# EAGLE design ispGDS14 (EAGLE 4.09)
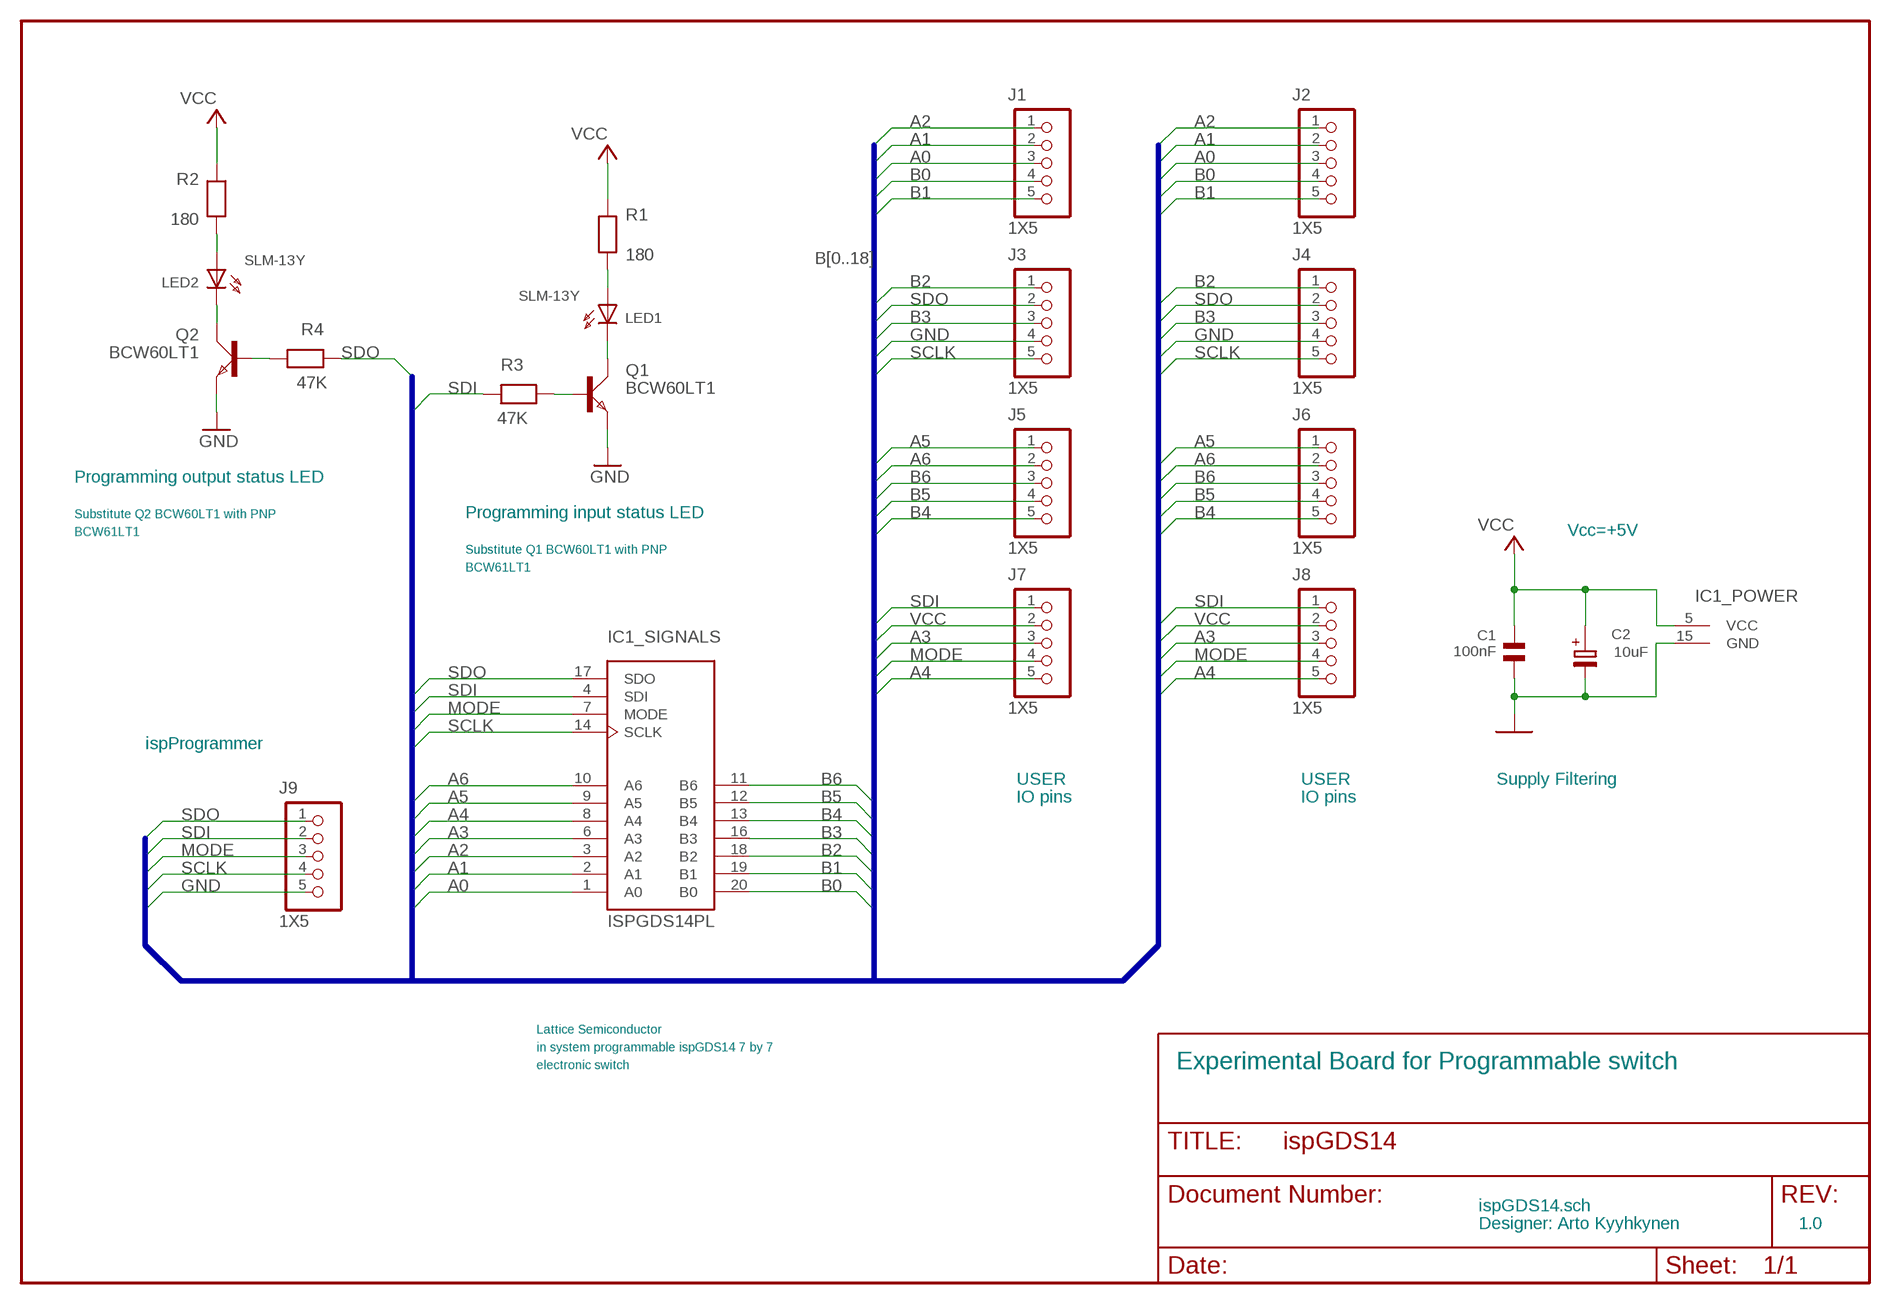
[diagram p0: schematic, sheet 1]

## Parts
C1  100nF  C2,5  [0603]
C2  10uF  CAP1210  [SMD1210]
IC1  ISPGDS14PL  [PLCC20S]
J1  1X5  [SIL5]
J2  1X5  [SIL5]
J3  1X5  [SIL5]
J4  1X5  [SIL5]
J5  1X5  [SIL5]
J6  1X5  [SIL5]
J7  1X5  [SIL5]
J8  1X5  [SIL5]
J9  1X5  [SIL5]
LED1  SLM-13Y  LEDSOT23  [SOT23]
LED2  SLM-13Y  LEDSOT23  [SOT23]
Q1  BCW60LT1  [SOT23]
Q2  BCW60LT1  [SOT23]
R1  180  RES  [0603]
R2  180  RES  [0603]
R3  47K  RES  [0603]
R4  47K  RES  [0603]

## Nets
A0: IC1.1(_SIGNALS:A0) J1.3 J2.3
A1: IC1.2(_SIGNALS:A1) J1.2 J2.2
A2: IC1.3(_SIGNALS:A2) J1.1 J2.1
A3: IC1.6(_SIGNALS:A3) J7.3 J8.3
A4: IC1.8(_SIGNALS:A4) J7.5 J8.5
A5: IC1.9(_SIGNALS:A5) J5.1 J6.1
A6: IC1.10(_SIGNALS:A6) J5.2 J6.2
B0: IC1.20(_SIGNALS:B0) J1.4 J2.4
B1: IC1.19(_SIGNALS:B1) J1.5 J2.5
B2: IC1.18(_SIGNALS:B2) J3.1 J4.1
B3: IC1.16(_SIGNALS:B3) J3.3 J4.3
B4: IC1.13(_SIGNALS:B4) J5.5 J6.5
B5: IC1.12(_SIGNALS:B5) J5.4 J6.4
B6: IC1.11(_SIGNALS:B6) J5.3 J6.3
GND: C1.1 C2.2(-) IC1.15(_POWER:GND) J3.4 J4.4 J9.5 Q1.1(E) Q2.1(E)
MODE: IC1.7(_SIGNALS:MODE) J7.4 J8.4 J9.3
N$1: LED1.2(A) R1.1
N$2: LED1.3(K) Q1.3(C)
N$3: LED2.3(K) Q2.3(C)
N$4: LED2.2(A) R2.1
N$5: Q1.2(B) R3.1
N$6: Q2.2(B) R4.1
SCLK: IC1.14(_SIGNALS:SCLK) J3.5 J4.5 J9.4
SDI: IC1.4(_SIGNALS:SDI) J7.1 J8.1 J9.2 R3.2
SDO: IC1.17(_SIGNALS:SDO) J3.2 J4.2 J9.1 R4.2
VCC: C1.2 C2.1(+) IC1.5(_POWER:VCC) J7.2 J8.2 R1.2 R2.2

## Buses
B[0..18]

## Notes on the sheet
- Programming output status LED
- Substitute Q2 BCW60LT1 with PNP | Programming input status LED
- BCW61LT1 | Vcc=+5V
- Substitute Q1 BCW60LT1 with PNP
- BCW61LT1
- ispProgrammer
- USER | USER | Supply Filtering
- IO pins | IO pins
- Lattice Semiconductor
- in system programmable ispGDS14 7 by 7
- electronic switch | Experimental Board for Programmable switch
- ispGDS14.sch
- Designer: Arto Kyyhkynen | 1.0

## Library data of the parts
C1 = cap:C2,5
C2 = user1:CAP1210
IC1 = user1:ISPGDS14PL
J1-J9 = demo:1X5
LED1 LED2 = user1:LEDSOT23
Q1 Q2 = user1:BCW60LT1
R1-R4 = demo:RES

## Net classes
0 default: width 0.406 mm, clearance 0.61 mm

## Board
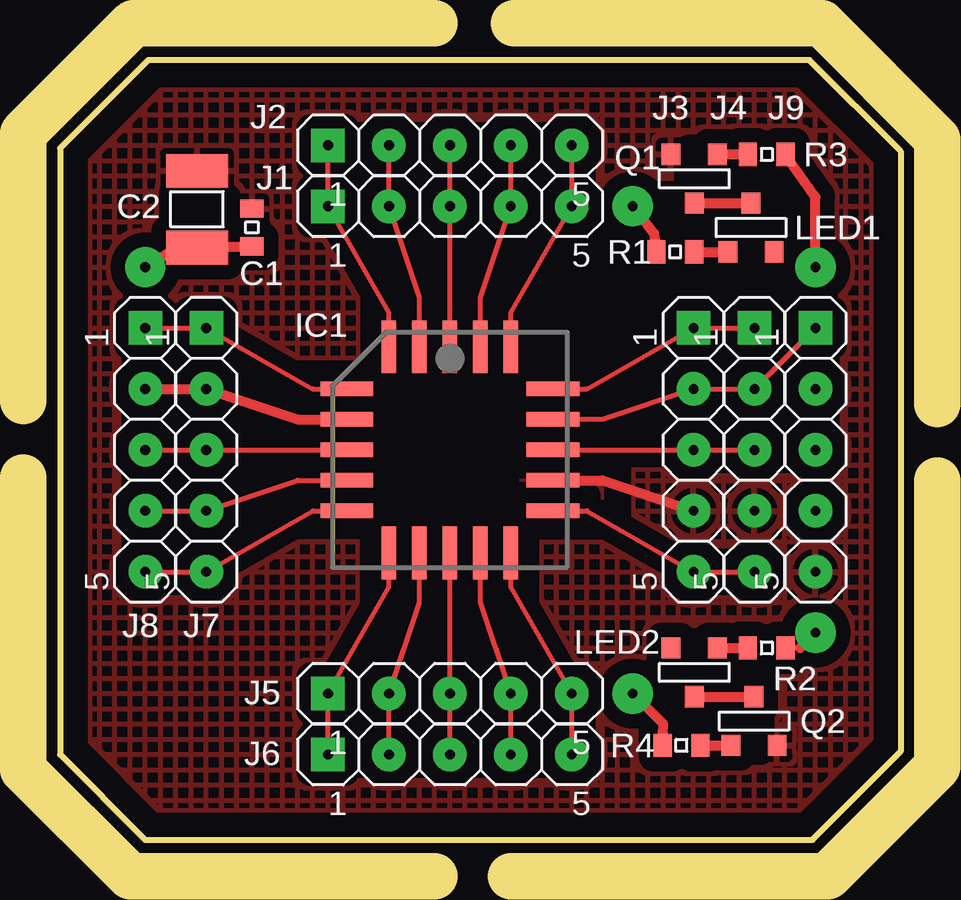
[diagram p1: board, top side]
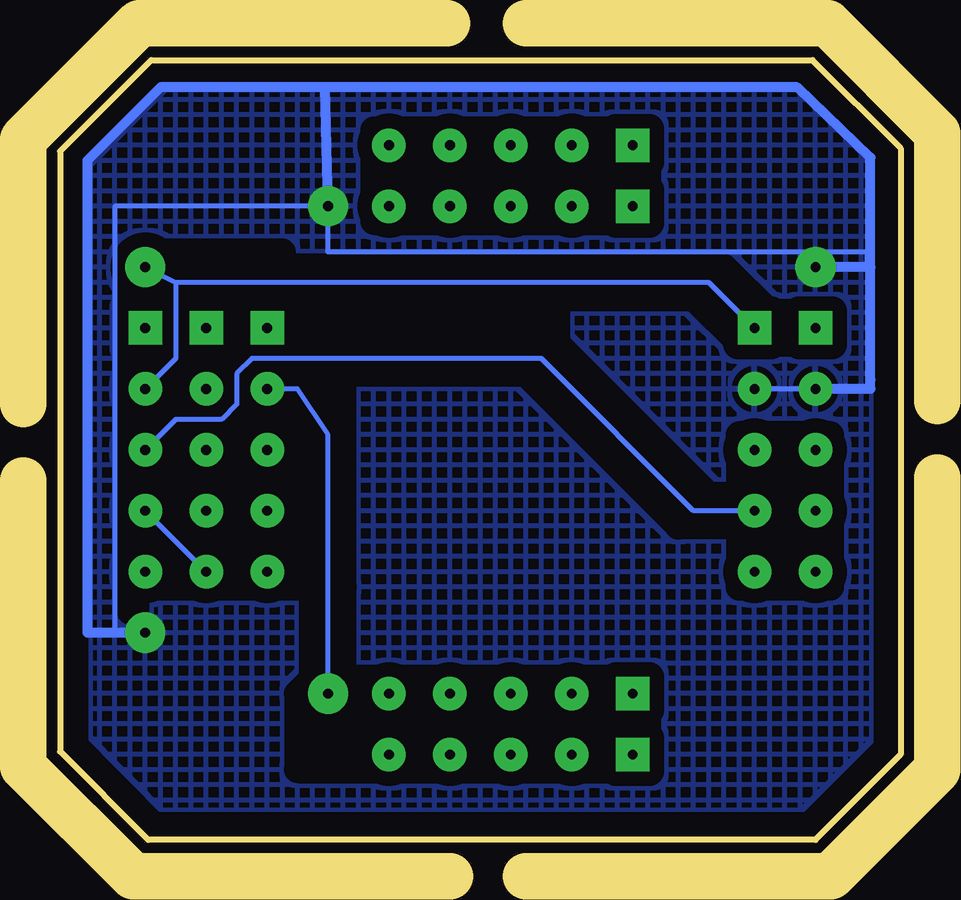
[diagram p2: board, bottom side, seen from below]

Size 35.05 x 32.51 mm. Coordinates in mm from the lower left corner, seen from the top.
Outline: 3.56,0 31.37,0 35.05,3.68 35.05,28.7 31.24,32.51 3.68,32.51 0,28.83 0,3.56 3.56,0
Copper layers used: Top, Bottom
tRestrict: area 13.7,18.2 to 18.8,18.8; area 13.7,17.5 to 18.8,18.2; area 13.7,14.4 to 18.8,18.2; area 13.7,13.7 to 18.8,18.8; area 13.7,13.7 to 18.8,18.8; 89 lines
bRestrict: area 2.9,10.5 to 6.7,16.9; area 10.5,25.8 to 22,29.6; area 14.4,20.7 to 25.1,22.6; area 10.5,2.9 to 25.1,6.7; area 23.2,9.5 to 32.1,24.5; 47 lines
Milling: 12 lines

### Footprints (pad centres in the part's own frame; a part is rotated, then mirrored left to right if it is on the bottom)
0603 = smd 0.762 x 0.965: 1 -0.787,0; 2 0.787,0
SMD1210 = smd 1.397 x 2.591: 1 -1.6,0; 2 1.6,0
PLCC20S = smd 0.6 x 2.2: 1 0,4.3; 2 -1.27,4.3; 3 -2.54,4.3; 9 -2.54,-4.3; 10 -1.27,-4.3; 11 0,-4.3; 12 1.27,-4.3; 13 2.54,-4.3; 19 2.54,4.3; 20 1.27,4.3 | smd 2.2 x 0.6: 4 -4.3,2.54; 5 -4.3,1.27; 6 -4.3,0; 7 -4.3,-1.27; 8 -4.3,-2.54; 14 4.3,-2.54; 15 4.3,-1.27; 16 4.3,0; 17 4.3,1.27; 18 4.3,2.54
SIL5 = drill 0.406 pad 1.397 square: 1 0,0 | drill 0.406 pad 1.397 round: 2 2.54,0; 3 5.08,0; 4 7.62,0; 5 10.16,0
SOT23 = smd 0.787 x 0.889: 1 -0.94,1.016; 2 0.991,1.016; 3 0.025,-1.016

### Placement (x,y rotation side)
C1  8,25.53 270 top
C2  5.71,26.29 90 top
IC1  16.26,16.26 0 top
J1  11.18,26.42 0 top
J2  11.18,28.96 0 top
J3  26.42,21.34 270 top
J4  28.96,21.34 270 top
J5  11.18,6.1 0 top
J6  11.18,3.56 0 top
J7  6.1,21.34 270 top
J8  3.56,21.34 270 top
J9  31.5,21.34 270 top
LED1  28.83,25.53 180 top
LED2  26.42,6.99 0 top
Q1  26.42,27.56 0 top
Q2  28.96,4.95 180 top
R1  25.65,24.51 180 top
R2  29.46,8 0 top
R3  29.46,28.57 0 top
R4  25.91,3.94 180 top

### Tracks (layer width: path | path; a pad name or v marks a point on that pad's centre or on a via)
A0
  Top 0.203: IC1.1 J1.3 J2.3
A1
  Top 0.203: IC1.2 14.99,22.61 J1.2 J2.2
A2
  Top 0.203: IC1.3 13.72,21.97 J1.1 J2.1
A3
  Top 0.203: IC1.6 J7.3 J8.3
A4
  Top 0.203: IC1.8 10.54,13.72 J7.5 J8.5
A5
  Top 0.203: IC1.9 13.72,10.54 J5.1 J6.1
A6
  Top 0.203: IC1.10 14.99,9.91 J5.2 J6.2
B0
  Top 0.203: IC1.20 17.53,22.61 J1.4 J2.4
B1
  Top 0.203: IC1.19 18.8,21.97 J1.5 J2.5
B2
  Top 0.203: IC1.18 21.97,18.8 J3.1 J4.1
B3
  Top 0.203: J4.3 J3.3 IC1.16
B4
  Top 0.203: IC1.13 18.8,10.54 J5.5 J6.5
B5
  Top 0.203: IC1.12 17.53,9.91 J5.4 J6.4
B6
  Top 0.203: IC1.11 J5.3 J6.3
GND
  Top 0.406: IC1.15 22.61,14.99 J3.4
  pour Top (isolate 0.356, hatched): 4.19,31.5 30.86,31.5 34.04,28.32 34.04,4.19 30.99,1.02 4.19,1.02 1.02,4.19 1.02,28.45
MODE
  Top 0.203: IC1.7 9.91,14.99 J7.4 J8.4
  Bottom 0.203: J9.3 30.23,17.53 28.32,17.53 27.69,18.16 27.69,19.43 27.05,20.07 14.99,20.07 8.64,13.72 J7.4
N$1
  Top 0.406: 26.42,24.51 R1.1 LED1.2
N$2
  Top 0.406: 28.83,26.54 LED1.3 Q1.3
N$3
  Top 0.406: 28.96,5.97 Q2.3 LED2.3
N$4
  Top 0.406: LED2.2 R2.1
N$5
  Top 0.406: Q1.2 R3.1
N$6
  Top 0.406: R4.1 Q2.2
SCLK
  Top 0.203: IC1.14 21.97,13.72 J3.5 J4.5
  Bottom 0.203: J4.5 J9.4
SDI  (via drill 0.41 pad 1.68)
  Top 0.203: J8.1 J7.1 10.54,18.8 IC1.4
  Top 0.406: 30.38,28.45 R3.2 30.23,28.57 31.5,26.8 v31.5,23.88
  Bottom 0.203: J9.2 30.23,20.07 30.23,23.24 | 30.23,23.24 v31.5,23.88 | 30.23,23.24 8,23.24 J7.1
SDO  (via drill 0.41 pad 1.68)
  Top 0.203: J9.1 J4.2 J3.2 22.61,17.53 IC1.17
  Top 0.406: R4.2 25.15,4.83 v23.88,6.1
  Bottom 0.203: v23.88,6.1 23.88,16.89 25.15,18.8 J3.2
VCC  (via drill 0.41 pad 1.68)
  Top 0.203: R1.2 24.77,25.27 24.77,24.51 | 30.86,8 R2.2
  Top 0.406: R1.2 24.77,24.51 | IC1.5 9.91,17.53 J7.2 J8.2 | 5.77,24.69 5.33,24.26 5.33,24.51 4.57,24.51 v3.56,23.88 | 5.77,24.69 5.84,24.77 5.87,24.74 C1.2 | 5.77,24.69 C2.1 | v31.5,8.64 30.86,8 | v23.88,26.42 24.77,25.27 24.89,24.51
  Bottom 0.203: J8.2 J7.2 | 1.27,19.18 1.4,24.51 23.88,24.51 v23.88,26.42 32.77,26.42 32.77,8.64 v31.5,8.64
  Bottom 0.406: 1.27,23.88 1.27,28.45 4.32,31.37 24,31.37 | 1.27,23.88 1.27,19.18 1.27,18.8 J8.2 | 1.27,23.88 v3.56,23.88 | v23.88,26.42 24,31.37 | 24,31.37 30.86,31.37 33.91,28.32 33.91,8.64 v31.5,8.64
  pour Bottom (isolate 0.356, hatched): 4.32,31.5 30.86,31.5 34.04,28.32 34.04,4.19 30.99,1.02 4.19,1.02 1.02,4.19 1.02,28.45

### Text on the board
tDocu: HEIGHT 1400 mils | WIDTH 1500 mils | Milling 78 mils | Grid 5 mils
_tNames: J2 | J3 | J4 | J9 | Q1 | R3 | C2 | J1 | R1 | LED1 | C1 | IC1 | J8 | J7 | LED2 | R2 | J5 | R4 | Q2 | J6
